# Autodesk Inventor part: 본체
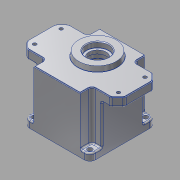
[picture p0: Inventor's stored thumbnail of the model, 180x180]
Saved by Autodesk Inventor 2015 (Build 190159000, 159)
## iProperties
Created: 2016-02
Part Number: 본체
Material: Aluminum 6061
Document SubType Name: Modeling
Designer: Administrator
Density: 2.7 g/cm^3
Appearance: Aluminum - Flat
Mass: 874.448 g
Surface Area: 762.038 cm^2
Volume: 323.869 cm^3
Author: Administrator
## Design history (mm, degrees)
sketch "Sketch1"
  geometry: L1 (-39, -47)-(39, -47); L2 (47, -39)-(47, 39); L3 (39, 47)-(-39, 47); L4 (-47, 39)-(-47, -39); L5 (-47, -47)-(47, 47); L6 (47, -47)-(-47, 47); C1 r 3.5 at (39, 39); C2 r 3.5 at (-39, 39); C3 r 3.5 at (-39, -39); C4 r 3.5 at (39, -39); A1 r 8 centre (-39, 39) between (-39, 47) and (-47, 39); A2 r 8 centre (-39, -39) between (-47, -39) and (-39, -47); A3 r 8 centre (39, -39) between (39, -47) and (47, -39); A4 r 8 centre (39, 39) between (47, 39) and (39, 47); 1 further point
  constraints: 12 end point, 8 centre point, 8 point on circle, 8 point on line, 8 tangent, 6 equal radius, 4 coincident, 2 midpoint, 2 parallel, 2 perpendicular, 1 horizontal
  dimensions: "d0" = 94 distance of L5.end L6.end; "d1" = 8 radius of A1; "d28" = 7 diameter of C1
extrude "Extrusion1" new body sketch "Sketch1" distance "d2" = 10; taper "d3" = 0 deg
sketch "Sketch2"
  geometry: L1 (-33, -47)-(33, -47); L2 (33, -47)-(33, 47); L3 (33, 47)-(-33, 47); L4 (-33, 47)-(-33, -47); L5 (-33, -47)-(33, 47); L6 (33, -47)-(-33, 47); L7 (-60, -30)-(60, -30); L8 (70, -20)-(70, 20); L9 (60, 30)-(-60, 30); L10 (-70, 20)-(-70, -20); L11 (-70, -30)-(70, 30); L12 (70, -30)-(-70, 30); L13 (60, 30)-(70, 20); L14 (70, -20)-(60, -30); L15 (-60, -30)-(-70, -20); L16 (-70, 20)-(-60, 30); 1 further point
  constraints: 32 end point, 8 point on line, 4 midpoint, 4 parallel, 2 horizontal, 2 perpendicular
  dimensions: "d4" = 60 distance of L12.start L11.end; "d5" = 140 distance of L11.end L12.end; "d6" = 66 distance of L2.end L3.end; "d7" = 94 distance of L1.end L2.end; "d8" = 10 distance of L9.start L11.end; "d9" = 10 distance of L8.end L11.end (= d8); "d10" = 10 distance of L8.start L12.start (= d8); "d11" = 10 distance of L7.end L12.start (= d10); "d12" = 10 distance of L7.start L11.start (= d8); "d13" = 10 distance of L10.end L11.start (= d12); "d14" = 10 distance of L10.start L12.end (= d8); "d15" = 10 distance of L9.end L12.end (= d14)
extrude "Extrusion2" join sketch "Sketch2" distance "d16" = 70; taper "d17" = 0 deg
sketch "Sketch4"
  geometry: L1 (60, 30)-(-60, 30) reference; L2 (-70, 20)-(-60, 30) reference; L3 (-70, 20)-(-70, -20) reference; L4 (-60, -30)-(-70, -20) reference; L5 (-60, -30)-(60, -30) reference; L6 (70, -20)-(60, -30) reference; L7 (70, -20)-(70, 20) reference; L8 (60, 30)-(70, 20) reference; 1 further point
extrude "Extrusion5" join sketch "Sketch4" distance "d29" = 13; taper "d30" = 0 deg
sketch "Sketch5"
  geometry: C1 r 28 at (0, 11); 1 further point
  constraints: 1 centre point, 1 vertical alignment
  dimensions: "d31" = 11 distance of point (0, 0) C1.centre; "d32" = 56 diameter of C1
extrude "Extrusion6" join sketch "Sketch5" distance "d33" = 7; taper "d34" = -10 deg
sketch "Sketch8"
  geometry: C1 r 2.5 at (60, 19); C2 r 2.5 at (60, -19); C3 r 2.5 at (-60, -19); C4 r 2.5 at (-60, 19); 1 further point
  constraints: 4 centre point, 3 equal radius, 2 horizontal alignment, 2 vertical alignment
  dimensions: "d39" = 5 diameter of C4; "d40" = 120 distance of C4.centre C1.centre; "d41" = 60 horizontal distance of C4.centre point (0, 0) (= 0.5 x d40); "d42" = 38 distance of C4.centre C3.centre; "d43" = 19 vertical distance of C3.centre point (0, 0)
extrude "Extrusion7" cut sketch "Sketch8" distance "d44" = 9; taper "d45" = 0 deg
sketch "Sketch9"
  geometry: C1 r 2.5 at (-60, -19) reference; C2 r 2.5 at (60, -19) reference; C3 r 2.5 at (60, 19) reference; C4 r 2.5 at (-60, 19) reference; C5 r 4.5 at (-60, 19); C6 r 4.5 at (-60, -19); C7 r 4.5 at (60, 19); C8 r 4.5 at (60, -19); 1 further point
  constraints: 4 centre point, 4 coincident, 3 equal radius
  dimensions: "d46" = 9 diameter of C5
extrude "Extrusion8" cut sketch "Sketch9" distance "d47" = 4; taper "d48" = 0 deg
sketch "Sketch10"
  geometry: C1 r 43 at (0, 0); 1 further point
  constraints: 1 centre point, 1 coincident
  dimensions: "d49" = 86 diameter of C1
extrude "Extrusion9" cut sketch "Sketch10" distance "d50" = 9; taper "d51" = 0 deg
sketch "Sketch12"
  geometry: L1 (-47, -30)-(47, -30); L2 (47, -30)-(47, 30); L3 (47, 30)-(-47, 30); L4 (-47, 30)-(-47, -30); L5 (-47, -30)-(47, 30); L6 (47, -30)-(-47, 30); 1 further point
  constraints: 12 end point, 2 midpoint, 2 parallel, 1 horizontal, 1 perpendicular
  dimensions: "d53" = 94 distance of L2.end L3.end; "d54" = 60 distance of L1.end L2.end
extrude "Extrusion10" join sketch "Sketch12" stored distance "d55" = 62; taper "d56" = 0 deg
sketch "Sketch13"
  geometry: C1 r 40 at (0, 0); 1 further point
  constraints: 1 centre point, 1 coincident
  dimensions: "d57" = 80 diameter of C1
extrude "Extrusion11" cut sketch "Sketch13" distance "d58" = 62; taper "d59" = 0 deg
sketch "Sketch14"
  geometry: C1 r 17.5 at (0, 11); C2 r 11 at (0, -20); A1 r 21 centre (0, 11) between (8.978, -7.984) and (-8.978, -7.984); A2 r 15 centre (0, -20) between (-8.978, -7.984) and (8.978, -7.984); 1 further point
  constraints: 4 centre point, 4 point on circle, 2 coincident, 2 vertical alignment
  dimensions: "d60" = 11 distance of point (0, 0) A1.centre; "d61" = 20 distance of point (0, 0) A2.centre; "d62" = 21 radius of A1; "d63" = 15 radius of A2; "d64" = 35 diameter of C1; "d65" = 22 diameter of C2
extrude "Extrusion12" join sketch "Sketch14" distance "d66" = 7; taper "d67" = 0 deg
hole "Hole1" diameter "d70" = 19; stored, may be unused: countersink angle "d74" = 90 deg, drill point angle "d76" = 0 deg; dims "d68" = 10, "d69" = 10, "d71" = 6, "d72" = 4, "d73" = 2, "d75" = 1
hole "Hole3" diameter "d88" = 25; stored, may be unused: countersink angle "d92" = 90 deg, drill point angle "d94" = 0 deg; dims "d86" = 10, "d87" = 10, "d89" = 6, "d90" = 32, "d91" = 8, "d93" = 13
hole "Hole4" diameter "d97" = 35; stored, may be unused: countersink angle "d101" = 90 deg, drill point angle "d103" = 0 deg; dims "d95" = 10, "d96" = 10, "d98" = 6, "d99" = 32, "d100" = 8, "d102" = 3
sketch "Sketch16"
  geometry: A1 r 36 centre (0, 0) between (-36, 0) and (36, 0); A2 r 4 centre (-36, 0) between (-35.778, -3.994) and (-35.852, 3.997); A3 r 4 centre (36, 0) between (35.852, 3.997) and (35.778, -3.994); A4 r 3.5 centre (-35.722, 7.495) between (-39.148, 8.214) and (-35.778, 3.995); A5 r 4 centre (-35.111, -7.95) between (-35.556, -3.975) and (-39.012, -8.834); A6 r 40 centre (0, 0) between (39.148, 8.214) and (39.012, -8.834) reference; A7 r 3.5 centre (35.722, 7.495) between (35.778, 3.995) and (39.148, 8.214); A8 r 4 centre (35.111, -7.95) between (39.012, -8.834) and (35.556, -3.975); 1 further point
  constraints: 26 point on circle, 8 tangent, 7 centre point, 4 equal radius, 2 horizontal alignment, 1 coincident
  dimensions: "d107" = 36 radius of A1; "d108" = 4 radius of A2; "d109" = 3.5 radius of A4
extrude "Extrusion14" join sketch "Sketch16" stored distance "d110" = 1; taper "d111" = 0 deg
sketch "Sketch17"
  geometry: A1 r 4 centre (-36, 0) between (-35.556, -3.975) and (-35.852, 3.997) reference; A2 r 4 centre (36, 0) between (35.852, 3.997) and (35.556, -3.975) reference; 1 further point
hole "Hole5" sketch "Sketch17" at (36, 0), (-36, 0) diameter "d112" = 3.242; stored, may be unused: countersink angle "d116" = 90 deg, drill point angle "d118" = 118 deg; dims "d113" = 7, "d114" = 32, "d115" = 8, "d117" = 9
fillet "Fillet1" dims "d119" = 0.3
fillet "Fillet2" dims "d120" = 5
chamfer "Chamfer1" distance "d121" = 1; stored, may be unused: second distance "d122" = 2, angle "d123" = 45 deg
fillet "Fillet3" dims "d124" = 2
fillet "Fillet4" dims "d125" = 2
fillet "Fillet5" dims "d126" = 2
sketch "Sketch18" dims "d0" = 94, "d1" = 8, "d28" = 7
  geometry: 2 further points
  constraints: 1 vertical alignment, 1 other
  dimensions: "d127" = 40 distance of point (39, 0) point (39, -40)
emboss "Emboss1" sketch "Sketch18" dims "d0" = 94, "d1" = 8, "d28" = 7, "d128" = 0.5, "d129" = 0
sketch "Sketch19"
  geometry: L1 (-33, 45)-(-33, 35) reference; L2 (-38, 30)-(-57.929, 30) reference; L3 (-61.464, 28.536)-(-68.536, 21.464) reference; L4 (-70, 17.929)-(-70, -17.929) reference; L5 (-68.536, -21.464)-(-61.464, -28.536) reference; L6 (-57.929, -30)-(-38, -30) reference; L7 (-33, -35)-(-33, -47) reference; L8 (-33, -47)-(33, -47) reference; L9 (33, -47)-(33, -35) reference; L10 (38, -30)-(57.929, -30) reference; L11 (61.464, -28.536)-(68.536, -21.464) reference; L12 (70, -17.929)-(70, 17.929) reference; L13 (68.536, 21.464)-(61.464, 28.536) reference; L14 (57.929, 30)-(38, 30) reference; L15 (33, 35)-(33, 45) reference; L16 (31, 47)-(-31, 47) reference; L17 (-32, 45)-(-32, 35); L18 (-38, 29)-(-57.929, 29); L19 (-60.757, 27.828)-(-67.828, 20.757); L20 (-69, 17.929)-(-69, -17.929); L21 (-67.828, -20.757)-(-60.757, -27.828); L22 (-57.929, -29)-(-38, -29); L23 (-32, -35)-(-32, -46); L24 (-32, -46)-(32, -46); L25 (32, -46)-(32, -35); L26 (38, -29)-(57.929, -29); L27 (60.757, -27.828)-(67.828, -20.757); L28 (69, -17.929)-(69, 17.929); L29 (67.828, 20.757)-(60.757, 27.828); L30 (57.929, 29)-(38, 29); L31 (32, 35)-(32, 45); L32 (31, 46)-(-31, 46); C1 r 28.252 at (0, 11) reference; C2 r 2.5 at (-60, -19) reference; C3 r 2.5 at (-60, 19) reference; C4 r 2.5 at (60, -19) reference; C5 r 2.5 at (60, 19) reference; A1 r 2 centre (-31, 45) between (-31, 47) and (-33, 45) reference; A2 r 5 centre (-38, 35) between (-38, 30) and (-33, 35) reference; A3 r 5 centre (-57.929, 25) between (-57.929, 30) and (-61.464, 28.536) reference; A4 r 5 centre (-65, 17.929) between (-68.536, 21.464) and (-70, 17.929) reference; A5 r 5 centre (-65, -17.929) between (-70, -17.929) and (-68.536, -21.464) reference; A6 r 5 centre (-57.929, -25) between (-61.464, -28.536) and (-57.929, -30) reference; A7 r 5 centre (-38, -35) between (-33, -35) and (-38, -30) reference; A8 r 5 centre (38, -35) between (38, -30) and (33, -35) reference; A9 r 5 centre (57.929, -25) between (57.929, -30) and (61.464, -28.536) reference; A10 r 5 centre (65, -17.929) between (68.536, -21.464) and (70, -17.929) reference; A11 r 5 centre (65, 17.929) between (70, 17.929) and (68.536, 21.464) reference; A12 r 5 centre (57.929, 25) between (61.464, 28.536) and (57.929, 30) reference; A13 r 5 centre (38, 35) between (33, 35) and (38, 30) reference; A14 r 2 centre (31, 45) between (33, 45) and (31, 47) reference; A15 r 1 centre (-31, 45) between (-31, 46) and (-32, 45); A16 r 6 centre (-38, 35) between (-38, 29) and (-32, 35); A17 r 4 centre (-57.929, 25) between (-57.929, 29) and (-60.757, 27.828); A18 r 4 centre (-65, 17.929) between (-67.828, 20.757) and (-69, 17.929); A19 r 4 centre (-65, -17.929) between (-69, -17.929) and (-67.828, -20.757); A20 r 4 centre (-57.929, -25) between (-60.757, -27.828) and (-57.929, -29); A21 r 6 centre (-38, -35) between (-32, -35) and (-38, -29); A22 r 6 centre (38, -35) between (38, -29) and (32, -35); A23 r 4 centre (57.929, -25) between (57.929, -29) and (60.757, -27.828); A24 r 4 centre (65, -17.929) between (67.828, -20.757) and (69, -17.929); A25 r 4 centre (65, 17.929) between (69, 17.929) and (67.828, 20.757); A26 r 4 centre (57.929, 25) between (60.757, 27.828) and (57.929, 29); A27 r 6 centre (38, 35) between (32, 35) and (38, 29); A28 r 1 centre (31, 45) between (32, 45) and (31, 46); 1 further point
  constraints: 32 end point, 28 point on circle, 14 centre point, 29 other
  dimensions: "d130" = 1 distance between parallel lines of L16 L32
extrude "Extrusion15" cut sketch "Sketch19" distance "d131" = 1; taper "d132" = 0 deg
fillet "Fillet6" dims "d133" = 2
fillet "Fillet7" dims "d134" = 2
sketch "Sketch20"
  geometry: C1 r 3.5 at (40, 40); C2 r 3.5 at (-40, 40); C3 r 3.5 at (-40, -40); C4 r 3.5 at (40, -40); 1 further point
  constraints: 4 centre point, 3 equal radius, 2 horizontal alignment, 2 vertical alignment
  dimensions: "d135" = 7 diameter of C1; "d136" = 80 distance of C4.centre C3.centre; "d137" = 40 horizontal distance of point (0, 0) C4.centre (= 0.5 x d136); "d138" = 80 distance of C1.centre C4.centre; "d139" = 40 horizontal distance of point (0, 0) C1.centre (= 0.5 x d138)
extrude "Extrusion16" cut sketch "Sketch20" stored distance "d140" = 1; taper "d141" = 0 deg
fillet "Fillet8" dims "d142" = 3
body "Solid1"
node "Projected Loop1"
